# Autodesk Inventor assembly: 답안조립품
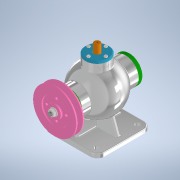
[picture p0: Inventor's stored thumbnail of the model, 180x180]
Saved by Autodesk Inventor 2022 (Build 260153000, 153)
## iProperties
Created: 2024-04
Part Number: 답안조립품
Document SubType Name: Assembly
Designer: user
Author: user
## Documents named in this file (16)
- C:\Users\user\Desktop\740406V1016\답안조립품.iam
- C:\Users\user\Desktop\740406V1016\본체.ipt
- C:\Users\user\Desktop\740406V1016\뒤커버.ipt
- C:\Users\user\Desktop\740406V1016\앞커버.ipt
- C:\Users\user\Desktop\740406V1016\상부커버.ipt
- C:\Users\user\Desktop\740406V1016\베어링- 6202.ipt
- KS B 2023 - 6202 - 15 x 35 x 11 - 7.8.ipt
- C:\Users\user\Desktop\740406V1016\칼라.ipt
- C:\Users\user\Desktop\740406V1016\편심축.ipt
- C:\Users\user\Desktop\740406V1016\키 4 x 4 x 12.ipt
- C:\Users\user\Desktop\740406V1016\오일실 15 30 7.ipt
- C:\Users\user\Desktop\740406V1016\V-벨트풀리.ipt
- C:\Users\user\Desktop\740406V1016\너트 M8.ipt
- C:\Users\user\Desktop\740406V1016\볼트 M4 x 16.ipt
- C:\Users\user\Desktop\740406V1016\볼트 M4 x 12.ipt
- C:\Users\user\Desktop\740406V1016\슬라이드.ipt
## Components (15 placed, 4 different names)
1. KS B 2023 - 6202 - 15 x 35 x 11 - 7.8:1
2. KS B 2023 - 6202 - 15 x 35 x 11 - 7.8:2
3. V-벨트풀리:1
4. ISO 4762 M4 x 16:1
5. ISO 4762 M4 x 16:2
6. ISO 4762 M4 x 16:3
7. ISO 4762 M4 x 16:4
8. ISO 4762 M4 x 16:5
9. ISO 4762 M4 x 16:6
10. ISO 4762 M4 x 16:7
11. ISO 4762 M4 x 16:8
12. KS B 1021 - 에 따름 ISO 1207 - 미터 A  M 4 x 12:1
13. KS B 1021 - 에 따름 ISO 1207 - 미터 A  M 4 x 12:2
14. KS B 1021 - 에 따름 ISO 1207 - 미터 A  M 4 x 12:3
15. KS B 1021 - 에 따름 ISO 1207 - 미터 A  M 4 x 12:4
